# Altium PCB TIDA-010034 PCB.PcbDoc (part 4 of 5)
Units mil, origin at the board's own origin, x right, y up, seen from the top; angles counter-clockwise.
Board outline 4497.63 x 4881.81 mil, 4 copper layers (Top Layer, Signal Layer 1, Signal Layer 2, Bottom Layer), stack 62.18 mil thick; 483 components, 240 nets, 1255 pads, 589 vias.
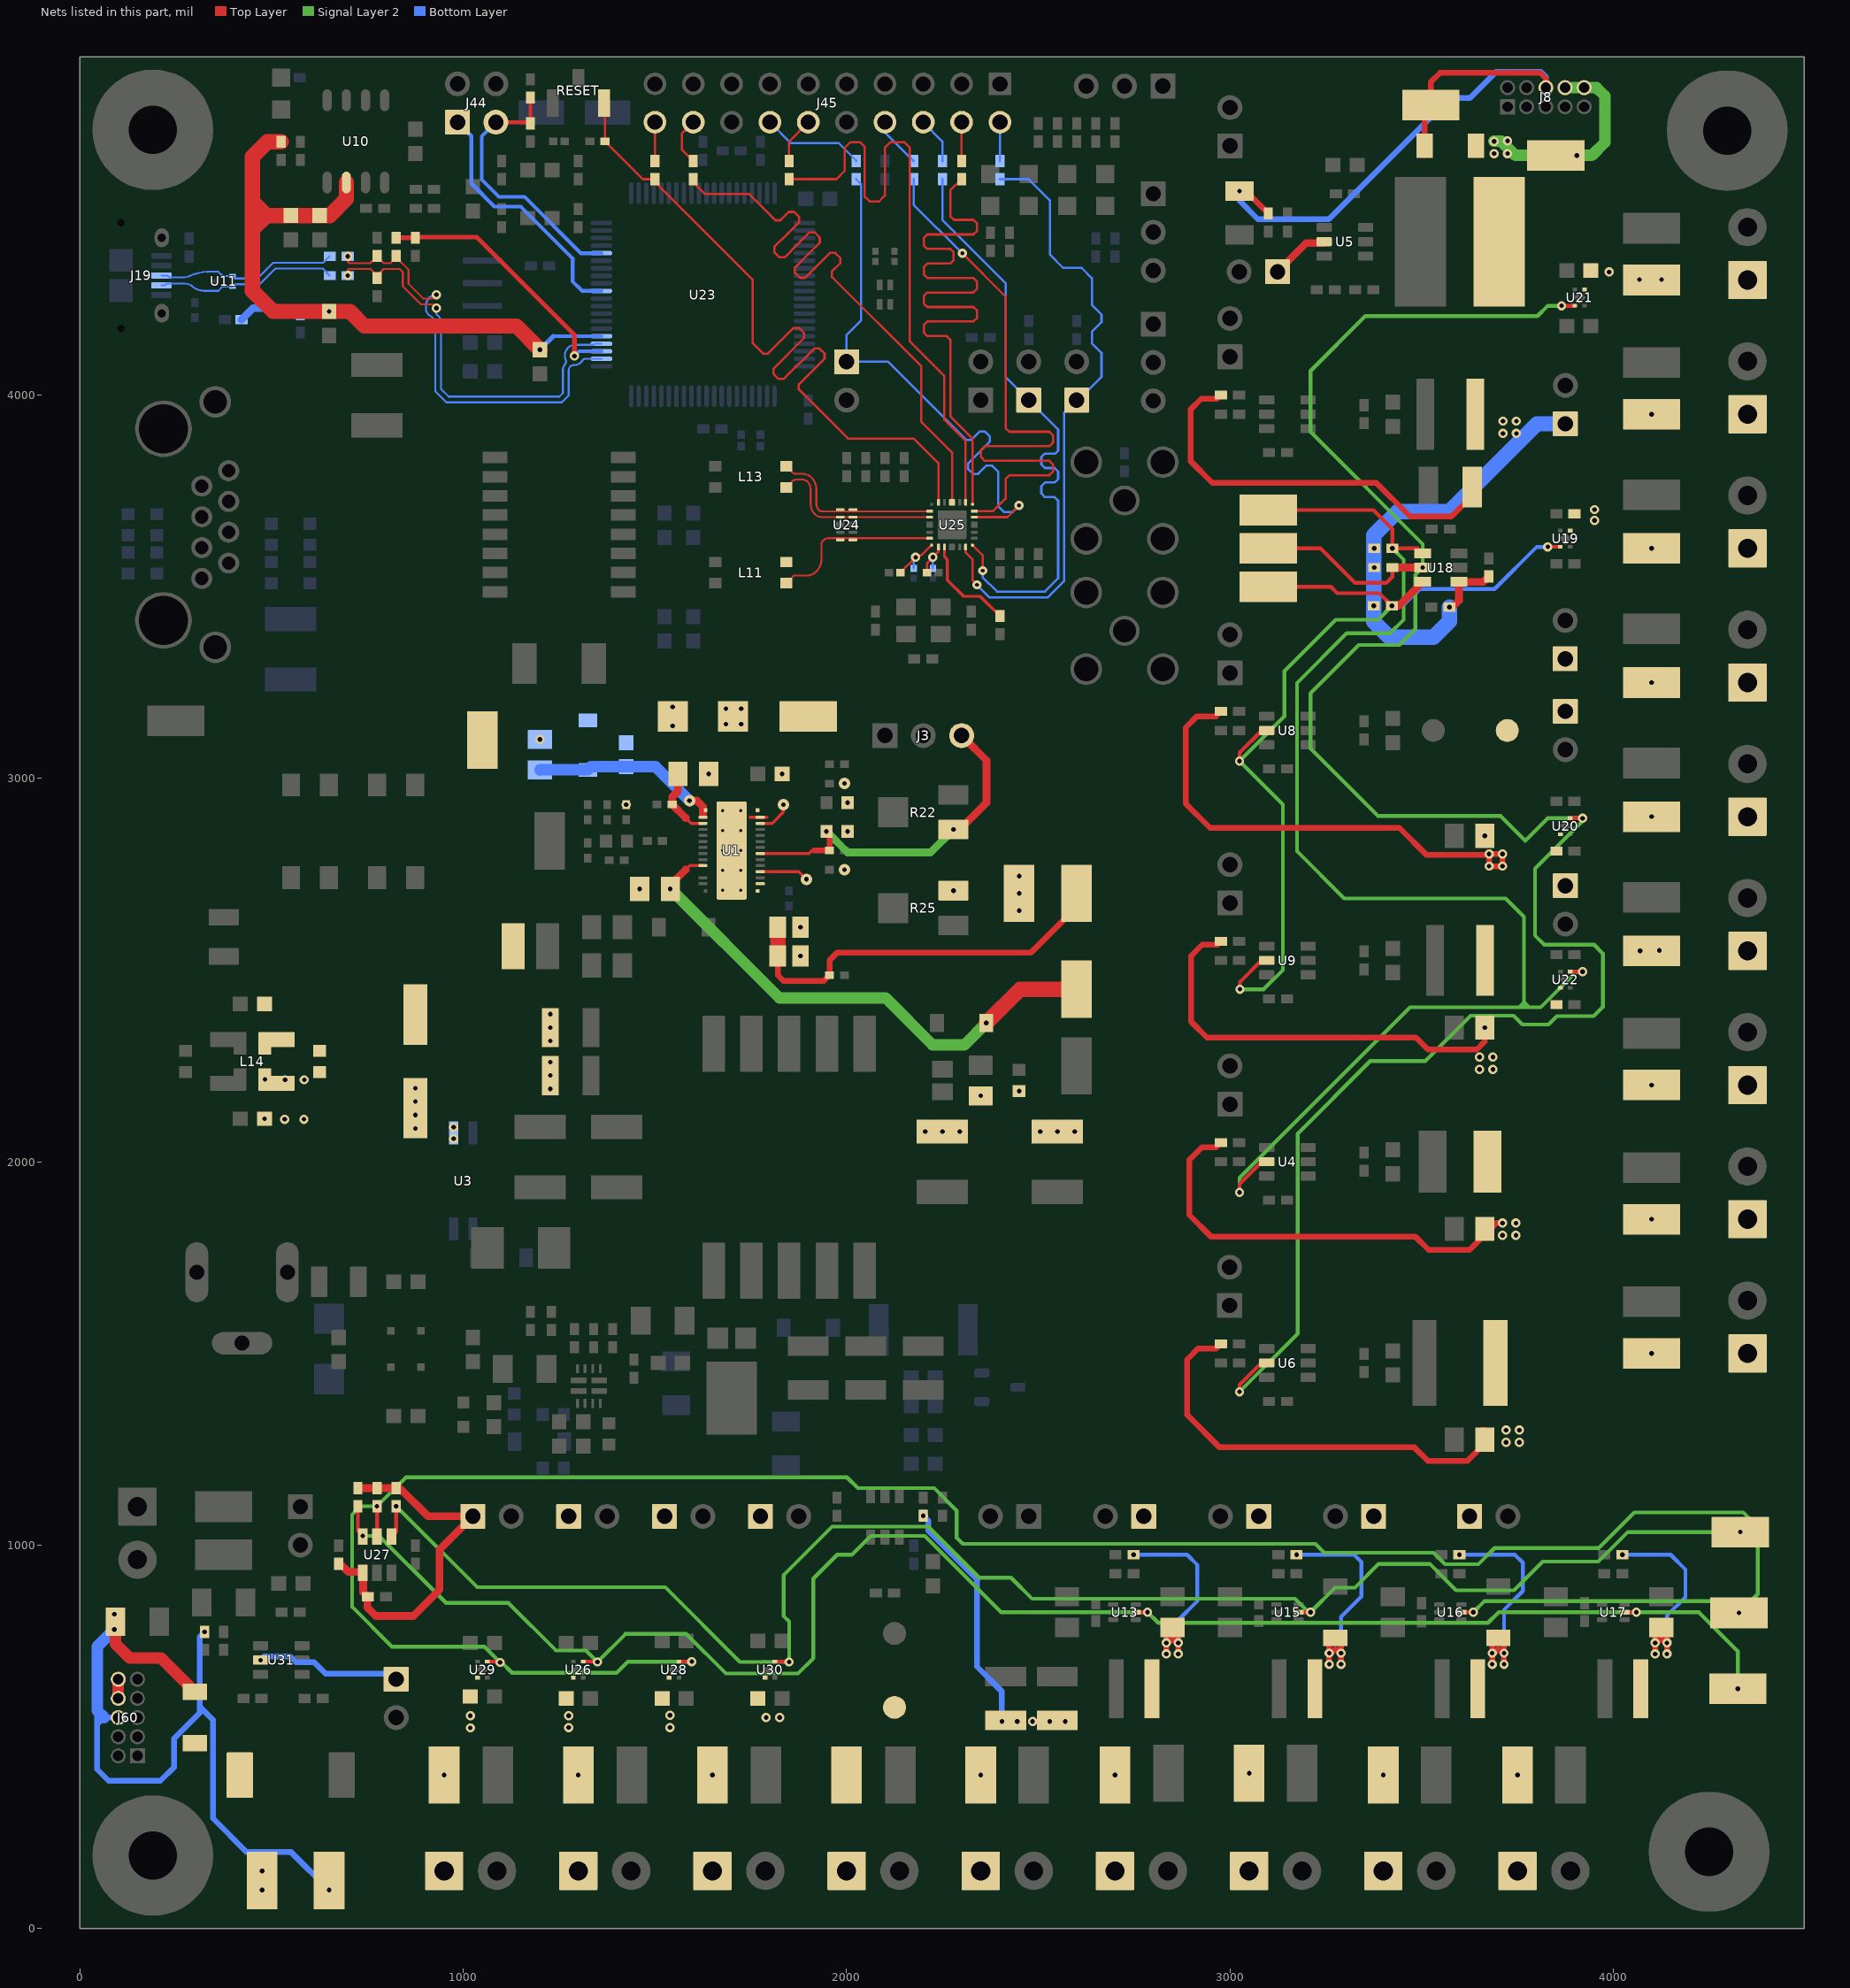
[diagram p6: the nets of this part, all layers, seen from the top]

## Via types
v1: diameter 24, hole 12, Top Layer to Bottom Layer, 451 vias
v2: diameter 30, hole 12, Top Layer to Bottom Layer, 86 vias
v3: diameter 24, hole 10, Top Layer to Bottom Layer, 22 vias
v4: diameter 19.68, hole 7.87, Top Layer to Bottom Layer, 10 vias
v5: diameter 20, hole 10, Top Layer to Bottom Layer, 8 vias
v6: diameter 19.69, hole 7.87, Top Layer to Bottom Layer, 5 vias
v7: diameter 18, hole 7.5, Top Layer to Bottom Layer, 3 vias
v8: diameter 20, hole 8, Top Layer to Bottom Layer, 2 vias
v9: diameter 34, hole 16, Top Layer to Bottom Layer, 2 vias

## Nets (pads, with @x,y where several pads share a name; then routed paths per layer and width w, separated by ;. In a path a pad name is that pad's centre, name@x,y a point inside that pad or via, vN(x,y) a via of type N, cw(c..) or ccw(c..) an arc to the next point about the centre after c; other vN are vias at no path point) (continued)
PGND: C4.2 C5.2 C6.2 C11.2 C13.2 C16.2 C24.2 C25.2 C27.1 C28.1 PGND.1 R5.1 R10.1 R11.1 R21.1 R25.1 R26.2 R28.1 U1.3 U1.11 U3.3 | length 220.7
  Top Layer w7.8: U1.3@1774.8,2756.69 1875.12,2756.69 v2(1895,2736.81) ; U1.11@1774.8,2882.68 1805.87,2882.68 1835,2911.81 v2(1835,2931.81)
  other v1: 975,2060 2205,2078.74 2250,2078.74 2295,2078.74 2505,2078.74 2550,2078.74 2595,2078.74 975,2090 2450,2655 2450,2700 2450,2745 1425,2931.5 1200,3101.81
  other v2: 875,2086.81 875,2121.81 875,2156.81 2350,2171.81 2450,2184.25 1226.85,2190 875,2191.81 1226.85,2225 1226.85,2260 1226.85,2315 1226.85,2350 1226.85,2385 1879.53,2536.81 1879.53,2611.81 2278.74,2707.09 1460,2711.81 1994.69,2761.81 2002.56,2861.81 2002.56,2936.81 1994.69,2986.81
PWDN: R87.2 U25.3 | length 1666.5
  Top Layer w6: R87.2@1600,4563.19 1600,4555 1630,4525 1745,4525 1807.5,4462.5 1814.2,4455.8 1827.59,4455.8 1849.57,4477.79 1862.96,4477.79 1876.35,4464.4 1876.35,4451.01 1847.67,4422.33 1811.49,4386.14 1811.49,4372.75 1824.88,4359.36 1838.27,4359.36 1874.45,4395.55 1903.14,4424.23 1916.53,4424.23 1929.92,4410.84 1929.92,4397.45 1901.23,4368.77 1865.05,4332.58 1865.05,4319.19 1878.44,4305.8 1891.83,4305.8 1928.01,4341.99 1956.7,4370.67 1970.09,4370.67 1983.48,4357.28 1983.48,4343.89 1961.49,4321.9 1961.49,4308.51 1965,4305 2195,4075 2195,3930 2275,3850 U25.3@2275,3719.88
PWDN_S: J45.18 R87.1 | length 126.2
  Top Layer w6: R87.1@1600,4610.43 1570,4640.43 1570,4681.81 J45.18@1600,4711.81
PWM1: J6.1 U5.5 | length 151.9
  Top Layer w20: J6.1@3124.02,4321.81 3199.02,4396.81 U5.5@3244.88,4396.81
PWM2: J58.1 U31.5 | length 383.1
  Bottom Layer w15: v1(470.87,700) 480.87,710 547.61,710 562.61,695 610,695 640,665 810,665 J58.1@825,650
RBIAS: R92.1 U25.14 | length 265.6
  Top Layer w7.87: U25.14@2255.32,3603.74 2255.32,3577.87 2263.19,3570 2263.19,3516.81 2305,3475 2348.62,3475 R92.1@2400,3423.62
RD_N: L13.4 U24.5 U24.6 U25.7 | length 456.3
  Top Layer w5: L13.4@1842.52,3814.37 1858.75,3798.14 ccw(c1868,3807.4) 1868,3794.31 1885.18,3794.31 cw(c1885.18,3761.18) 1908.61,3784.61 cw(c1878.69,3754.69) 1921,3754.69 1921,3716.82 ccw(c1945.34,3716.82) 1928.13,3699.6 ccw(c1934.73,3706.2) 1934.73,3696.87 2216.56,3696.87 U25.7@2216.93,3697.24
RD_P: L13.3 U24.4 U24.7 U25.8 | length 456.3
  Top Layer w5: L13.3@1842.52,3759.25 1858.75,3775.48 cw(c1868,3766.22) 1868,3779.31 1885.18,3779.31 cw(c1885.18,3761.18) 1898,3774 cw(c1878.69,3754.69) 1906,3754.69 1906,3716.82 ccw(c1945.34,3716.82) 1917.52,3689 ccw(c1934.73,3706.2) 1934.73,3681.87 2216.56,3681.87 U25.8@2216.93,3681.5
RESET: C123.2 R88.2 RESET.2 U25.5 | length 1969.3
  Top Layer w6: RESET.2@1366.93,4761.81 1369.69,4759.05 C123.2@1369.69,4661.81 1468.31,4563.19 R88.2@1500,4563.19 1500,4555 1755,4300 1755,4135 1775,4115 1781.7,4108.3 1795.09,4108.3 1862.07,4175.29 1875.46,4175.29 1888.85,4161.9 1888.85,4148.51 1815.17,4074.83 1808.99,4068.65 1808.99,4055.26 1822.38,4041.86 1835.77,4041.86 1841.95,4048.05 1915.64,4121.73 1929.03,4121.73 1942.42,4108.34 1942.42,4094.95 1875.43,4027.96 1875.43,4014.57 1880,4010 2003.19,3886.81 2175,3886.81 2239.57,3822.24 U25.5@2239.57,3719.88
RESET_S: J45.20 R88.1 | length 101.4
  Top Layer w6: R88.1@1500,4610.43 J45.20@1500,4711.81
RSNS: R10.2 R11.2 R13.2 RSNS.1 U1.1 U1.A1 | length 1048.6
  Top Layer w15: R10.2@1820.47,2536.81 1820.47,2486.34 1835,2471.81 1940.31,2471.81 R13.2@1955.32,2486.81 1955.32,2525.32 1975,2545 2480,2545 2600,2665 RSNS.1@2600,2700
  Top Layer w40: R10.2@1820.47,2536.81 R11.2@1820.47,2611.81
RST/SBWTDIO: C104.2 J44.3 R74.2 U23.76 | length 700.9
  Top Layer w10: J44.3@1085,4711.81 1171.81,4711.81 R74.2@1175,4715 ; R74.2@1175,4723.62 C104.2@1175,4776.38
  Bottom Layer w10: J44.3@1085,4711.81 1048,4674.81 1048,4562 1093,4517 1159.81,4517 1306.73,4370.08 U23.76@1360.24,4370.08
RX_D0: J52.1 R82.2 U25.18 | length 1619.7
  Top Layer w6: U25.18@2328.15,3608.66 2355,3581.81 v3(2355,3541.81)
  Bottom Layer w6: R82.2@2250,4563.19 2250,4456.81 2415,4291.81 2415,4046.81 J52.1@2475,3986.81 2551.81,3910 2551.81,3855 2544.37,3847.56 2517.47,3847.56 2508,3838.09 2508,3819.15 2517.47,3809.68 2542.34,3809.68 2551.81,3800.22 2551.81,3781.28 2542.34,3771.81 2517.47,3771.81 2508,3762.34 2508,3743.41 2517.47,3733.94 2542.34,3733.94 2551.81,3724.47 2551.81,3715 2551.81,3521.81 2517.56,3487.56 2392.44,3487.56 2355,3525 v3(2355,3541.81)
RX_D0_S: J45.6 R82.1 | length 122.1
  Bottom Layer w6: J45.6@2200,4711.81 2250,4661.81 R82.1@2250,4610.43
RX_D1: J51.1 R80.2 U25.17 | length 1664.1
  Top Layer w6: U25.17@2310.43,3603.74 2310.43,3589.57 2328.81,3571.19 2328.81,3516.19 v3(2340,3505)
  Bottom Layer w6: v3(2340,3505) 2373.19,3471.81 2524.08,3471.81 2567.56,3515.29 2567.56,3954.37 J51.1@2600,3986.81 2605,3986.81 2665,4046.81 2665,4110 2640,4135 2640,4165 2665,4190 2665,4210 2640,4235 2640,4305 2613.19,4331.81 2565,4331.81 2530,4366.81 2530,4508.19 2475,4563.19 R80.2@2400,4563.19
RX_D1_S: J45.2 R80.1 | length 101.4
  Bottom Layer w6: R80.1@2400,4610.43 J45.2@2400,4711.81
RX_ER: J49.1 R86.2 U25.22 | length 1465.3
  Top Layer w6: U25.22@2333.07,3681.5 2419.69,3681.5 v3(2450,3711.81)
  Bottom Layer w6: R86.2@2025,4563.19 2037.5,4550.69 2037.5,4194.31 2000,4156.81 J49.1@2000,4086.81 2108.19,4086.81 2285.22,3909.78 2298.61,3896.39 2305,3890 2311.7,3883.3 2325.09,3883.3 2347.05,3905.27 2360.44,3905.27 2373.83,3891.88 2373.83,3878.49 2345.17,3849.83 2316.51,3821.17 2316.51,3807.78 2329.9,3794.39 2343.29,3794.39 2365.26,3816.35 2378.65,3816.35 2387.5,3807.5 2395,3800 2395,3710 2410,3695 2433.19,3695 v3(2450,3711.81)
RX_ER_S: J45.14 R86.1 | length 267.8
  Bottom Layer w6: J45.14@1800,4711.81 1855,4656.81 1980,4656.81 2025,4611.81 R86.1@2025,4610.43
SEQ1_FLAG1: R66.1 SEQ1_FLAG1.1 U8.5 U9.5 U18.6 U19.3 | length 2540.4
  Top Layer w10: v1(3025,3045) 3025,3067 3083,3125 U8.5@3095.87,3125 ; v1(3026,2450) 3026,2469 3082,2525 U9.5@3095.87,2525 ; SEQ1_FLAG1.1@3100,3500 3263,3500 3280,3483 3389.64,3483 v1(3422.64,3450) ; v1(3829,3604) 3832.71,3604 3832.86,3604.14 U19.3@3861.76,3604.14
  Top Layer w20: v1(3422.64,3450) 3440.16,3450 U18.6@3502.76,3512.6
  Signal Layer 2 w10: v1(3026,2450) 3088,2450 3138,2500 3138,2932 v1(3025,3045) 3142,3162 3142,3280 3276,3414 3386.64,3414 v1(3422.64,3450)
  Bottom Layer w10: v1(3422.64,3450) 3451,3450 3495,3494 3690.27,3494 3800.27,3604 v1(3829,3604)
SEQ1_FLAG2: R67.1 SEQ1_FLAG2.1 U6.5 U18.5 U20.3 U21.3 | length 5880
  Top Layer w10: v1(3025,1400) 3025,1418 3082,1475 U6.5@3095.87,1475 ; SEQ1_FLAG2.1@3100,3600 3236,3600 3326,3510 3408,3510 3423.62,3525.62 R67.1@3423.62,3550 ; v1(3865.06,4232.96) U21.3@3899.5,4232.96 ; U20.3@3887.8,2896.06 3919.94,2896.06 v1(3920,2896)
  Top Layer w20: R67.1@3423.62,3550 v1(3502.76,3550)
  Signal Layer 2 w10: v1(3025,1400) 3177,1552 3177,2073.56 3366,2262.56 3509.56,2262.56 3628,2381 3740,2381 3763,2358 3831,2358 3852.87,2379.87 3948.87,2379.87 3972.63,2403.63 3972.63,2543.37 3950,2566 3820,2566 3795.87,2590.13 3795.87,2764.87 3920,2889 v1(3920,2896) 3828.8,2896 3770.4,2837.6 3706,2902 3386,2902 3210,3078 3210,3222 3336,3348 3442,3348 3484,3390 3484,3531.24 v1(3502.76,3550) 3502.76,3611.24 3210,3904 3210,4063 3353,4206 3802,4206 3828.96,4232.96 v1(3865.06,4232.96)
SEQ1_FLAG3: R68.1 SEQ1_FLAG3.1 U4.5 U18.4 U22.3 | length 3703.1
  Top Layer w10: v1(3025,1920) 3025,1942 3083,2000 U4.5@3095.87,2000 ; SEQ1_FLAG3.1@3100,3700 3374,3700 3423.62,3650.38 v1(3423.62,3600) 3490.16,3600 U18.4@3502.76,3587.4 ; U22.3@3887.8,2496.06 v1@3919.72,2496.06
  Signal Layer 2 w10: v1(3025,1920) 3025,1958 3470,2403 3755,2403 ; v1(3423.62,3600) 3453,3570.62 3453,3414 3418,3379 3305,3379 3175,3249 3175,2810 3298,2687 3719,2687 3767,2639 3767,2416.46 ; 3780.46,2403 3767,2416.46 ; v1(3920,2495.79) 3903.36,2495.79 3810.58,2403 3764,2403 ; 3755,2403 3764,2403 ; 3755,2403 3767,2415 ; 3764,2403 3767,2406 3767,2415 ; 3767,2415 3767,2416.46
SEQ2_FLAG1: R113.1 SEQ2_FLAG1.1 U13.5 U17.5 U26.3 U27.6 | length 4495.1
  Top Layer w10: R113.1@725,1101.38 725,1036.65 v1(737.6,1024.06) ; U26.3@1312.8,696.06 1348.94,696.06 v1(1350,695) ; U13.5@2754.13,825 v1(2785,825) ; U17.5@4029.13,825 v1(4060,825)
  Signal Layer 2 w10: v1(737.6,1024.06) 779.97,1024.06 955.02,849 1117.73,849 1241.73,725 1320,725 v1(1350,695) 1423,768 1582.02,768 1685.02,665 1873.45,665 1913,704.55 1913,912.69 1975.31,975 2014.01,975 2063.06,1024.06 2203.94,1024.06 2403,825 v1(2785,825) 2813,797 3673,797 3701,825 v1(4060,825) 4223,825 4325,723 v1(4325,625)
SEQ2_FLAG2: R114.1 SEQ2_FLAG2.1 U16.5 U27.5 U28.3 U29.3 | length 6263.8
  Top Layer w10: U27.5@775,1022.24 v1(775,1101.38) ; U29.3@1062.8,696.06 1093.94,696.06 v1(1096,694) ; U28.3@1562.8,696.06 v1@1595.94,696.06 ; U16.5@3604.14,825 v1(3635,825)
  Signal Layer 2 w10: v1(1596,696) 1429.46,696 1400.07,666.61 1127.39,666.61 1100,694 v1(1096,694) 1055,735 814,735 710,839 710,1079 732.38,1101.38 v1(775,1101.38) 850.62,1177 2001,1177 2029.5,1148.5 2228.5,1148.5 2287,1090 2287,1019 2303,1003 3223,1003 3246,980 3531,980 3561,950 3648,950 3690,992 3962,992 4055,1085 4339,1085 4377,1047 4377,872 v1(4328,823) 4297,854 3664.01,854 v1(3635,825)
SEQ2_FLAG3: R115.1 SEQ2_FLAG3.1 U15.5 U27.4 U30.3 | length 4362.7
  Top Layer w10: U27.4@812.4,1022.24 825,1034.84 v1(825,1101.38) ; U30.3@1812.8,696.06 1848.94,696.06 v1(1850,695) ; U15.5@3179.13,825 v1(3210,825)
  Signal Layer 2 w10: v1(825,1101.38) 1036.38,890 1526.73,890 1721.73,695 v1(1850,695) 1850,800.63 1835.5,815.13 1835.5,921.5 1962,1048 2213,1048 2346,915 2429,915 2484,860 3170,860 3205,825 v1(3210,825) 3274,889 3326,889 3388,951 3521,951 3590,882 3741,882 3816,957 3961,957 4038,1034 v1(4331,1034)
TARGET_D_N: C114.1 R78.1 U23.64 | length 1089.6
  Top Layer w5: v1(698.62,4311.81) 698.62,4325.62 702,4329 758,4329 C114.1@775,4312 ; C114.1@775,4305.43 C114.1@775,4312 ; v1(930,4226.81) 919.81,4237 889.07,4237 842,4284.07 842,4320.79 833.79,4329 792,4329 C114.1@775,4312
  Bottom Layer w5: v1(930,4226.81) ccw(c943.24,4219.17) 934,4207 cw(c919.21,4189.66) 942,4190 942,4016 961.91,3996.09 1250.83,3996.09 1260,4005.26 1260,4018 1260,4067 cw(c1282.6,4065.6) 1264.46,4079.15 ccw(c1255.15,4088.06) 1267.71,4090.93 cw(c1294.83,4103.77) 1264.85,4102.54 cw(c1292.15,4103.7) 1291,4131 1340,4131 1342.86,4133.86 U23.64@1360.24,4133.86
TARGET_D_P: C113.1 R75.2 R79.1 U23.62 | length 1151.4
  Top Layer w5: v1(698.62,4361.81) 698.62,4348.38 703,4344 757.16,4344 775,4361.84 C113.1@775,4363.19 ; C113.1@775,4361.82 792.82,4344 810,4344 R75.2@825,4359 ; R75.2@825,4363.19 R75.2@825,4359 ; v1(930,4261.81) 920.19,4252 895.28,4252 857,4290.28 857,4327 R75.2@825,4359
  Bottom Layer w5: v1(930,4261.81) ccw(c930,4234.81) 903,4234.81 903,4220 ccw(c929.64,4229.18) 917,4204 919.93,4201.07 cw(c902.86,4184) 927,4184 927,4009.79 955.7,3981.09 1257.05,3981.09 1275,3999.04 1275,4065 cw(c1288,4065) 1288,4078 ccw(c1288.93,4103.64) 1309.66,4088.52 cw(c1317.88,4085.87) 1318.49,4094.49 U23.62@1360.24,4094.49
TARGET_PUR: R75.1 R76.1 U23.63 | length 701
  Top Layer w12: R75.1@825,4410.43 R76.1@875,4410.43 ; R76.1@875,4411.81 1035,4411.81 1290,4156.81 v1(1290,4101.81)
  Bottom Layer w10: v1(1290,4101.81) 1302.36,4114.18 U23.63@1360.24,4114.18
TD_N: U24.2 U24.9 U25.10 | length 455
  Top Layer w5: 1842.52,3564.37 1860.87,3546.02 ; 1860.88,3546.01 ccw(c1865,3550.16) 1865,3544.31 1896.36,3544.31 ccw(c1896.36,3563.6) 1910,3549.96 ccw(c1887.59,3572.37) 1919.28,3572.37 1919.28,3609.61 cw(c1950.39,3609.61) 1928.39,3631.61 cw(c1952.89,3607.11) 1952.89,3641.75 2216.56,3641.75 U25.10@2216.93,3642.13
TD_N: L11.4
TD_P: L11.3 U24.1 U24.10 U25.11 | length 455
  Top Layer w5: L11.3@1842.52,3509.25 1860.87,3527.6 ; 1860.88,3527.61 cw(c1865,3523.47) 1865,3529.31 1896.36,3529.31 ccw(c1896.36,3563.6) 1920.61,3539.35 ccw(c1887.59,3572.37) 1934.28,3572.37 1934.28,3609.61 cw(c1950.39,3609.61) 1939,3621 cw(c1952.89,3607.11) 1952.89,3626.75 2216.56,3626.75 U25.11@2216.93,3626.38
TEST/SBWTCK: J44.1 U23.71 | length 665.2
  Bottom Layer w10: J44.1@985,4711.81 1021,4675.81 1021,4552 1081.19,4491.81 1150,4491.81 1285,4356.81 1285,4296.81 1310.16,4271.66 U23.71@1360.24,4271.66
TX_D0: R83.2 U25.23 | length 1605.4
  Top Layer w6: v3(2301.81,4370) 2415,4256.81 2415,3923.22 2415,3913.75 2424.47,3904.28 2528.87,3904.28 2538.34,3894.81 2538.34,3875.87 2528.87,3866.41 2415,3866.41 2360.3,3866.41 2350.83,3856.94 2350.83,3838 2360.3,3828.53 2415,3828.53 2528.87,3828.53 2538.34,3819.06 2538.34,3800.13 2528.87,3790.66 2424.47,3790.66 2415,3781.19 2415,3780 2415,3730 2382.24,3697.24 U25.23@2333.07,3697.24
  Bottom Layer w6: R83.2@2175,4563.19 2175,4496.81 v3(2301.81,4370)
TX_D0_S: J45.8 R83.1 | length 132.4
  Bottom Layer w6: J45.8@2100,4711.81 2100,4685.43 R83.1@2175,4610.43
TX_D1: R81.2 U25.24 | length 1775
  Top Layer w6: R81.2@2300,4563.19 2270.75,4533.94 2270.75,4495 2270.75,4466.4 2280.22,4456.93 2330.77,4456.93 2340.24,4447.46 2340.24,4428.52 2330.77,4419.05 2270.75,4419.05 2210.73,4419.05 2201.26,4409.59 2201.26,4390.65 2210.73,4381.18 2270.75,4381.18 2278.94,4372.99 2278.94,4351.5 2270.75,4343.31 2210.73,4343.31 2201.26,4333.84 2201.26,4314.9 2210.73,4305.43 2270.75,4305.43 2330.77,4305.43 2340.24,4295.96 2340.24,4277.03 2330.77,4267.56 2270.75,4267.56 2210.73,4267.56 2201.26,4258.09 2201.26,4239.15 2210.73,4229.68 2270.75,4229.68 2330.77,4229.68 2340.24,4220.22 2340.24,4201.28 2330.77,4191.81 2270.75,4191.81 2210.73,4191.81 2201.26,4182.34 2201.26,4163.41 2210.73,4153.94 2261.28,4153.94 2270.75,4144.47 2270.75,4135 2270.75,3944.25 2328.15,3886.85 U25.24@2328.15,3714.96
TX_D1_S: J45.4 R81.1 | length 101.4
  Top Layer w6: R81.1@2300,4610.43 J45.4@2300,4711.81
TX_EN: R85.2 U25.1 | length 1659.7
  Top Layer w6: R85.2@1850,4563.19 1973.19,4563.19 1995,4585 1995,4645 2010,4660 2035,4660 2046.65,4648.35 2046.65,4518.35 2060,4505 2085,4505 2100,4520 2100,4645 2115,4660 2150,4660 2165,4645 2165,4140 2255,4050 2255,3935 2310.43,3879.57 2310.43,3871.99 2310.5,3871.93 2310.5,3765.06 2310.43,3765 U25.1@2310.43,3719.88
TX_EN_S: J45.12 R85.1 | length 122.1
  Top Layer w6: R85.1@1850,4610.43 1850,4661.81 J45.12@1900,4711.81
USB_N: J19.2 R78.2 U11.2 | length 484.1
  Bottom Layer w5: J19.2@212.4,4286.22 221.22,4286.22 226,4291 269.77,4291 cw(c271.29,4253.72) 290,4286 ccw(c324.7,4321.8) 322.31,4272 337.02,4271.96 ; R78.2@651.38,4311.81 633.19,4330 510,4330 469,4289 403.61,4289 U11.2@397.64,4283.03 372.03,4283.03 360.94,4271.94 344.01,4271.94 ; 337.02,4271.96 344.01,4271.94 ; 337.02,4271.94 344.01,4271.94
USB_P: J19.3 R79.2 U11.1 | length 474.4
  Bottom Layer w5: J19.3@212.4,4311.81 228.19,4311.81 233,4307 268,4307 ccw(c269.52,4344.28) 288.23,4312 cw(c338.97,4185.26) 344.01,4321.69 360.94,4321.69 372.03,4310.59 U11.1@397.64,4310.59 404.23,4304 463,4304 504,4345 634.57,4345 R79.2@651.38,4361.81
USB_VBUS: C64.1 C65.1 C70.1 C71.1 C107.2 D12.1 D13.1 R49.2 U10.2 U23.65 | length 2052.7
  Top Layer w40: R49.2@525,4660.43 488.62,4660.43 450,4621.81 450,4504.8 ; U10.2@695,4554.53 695,4511.81 651.5,4468.31 C64.1@625,4468.31 C65.1@550,4468.31 486.5,4468.31 ; v2(1200,4118.31) 1138.31,4180 741.81,4180 703.5,4218.31 v2(650,4218.31) 503.5,4218.31 450,4271.81 450,4431.81 ; 450,4431.81 450,4504.8 ; 450,4431.81 486.5,4468.31 ; 450,4504.8 486.5,4468.31
  Bottom Layer w10: 1235.24,4153.55 U23.65@1360.24,4153.55
  Bottom Layer w12: v2(1200,4118.31) 1235.24,4153.55
  Bottom Layer w20: D12.1@421.65,4196.81 451.65,4226.81 558.62,4226.81 C70.1@575,4210.43 582.87,4218.31 v2(650,4218.31)
VB: C25.1 J3.3 R22.3 R23.1 U1.6 | length 919
  Top Layer w7.8: U1.6@1774.8,2803.94 1902.13,2803.94 1910,2811.81 1915,2811.81
  Top Layer w15: 1915,2811.81 R23.1@1955.32,2811.81 1955.32,2853.94 v2(1947.44,2861.81)
  Top Layer w20: v2(2278.74,2866.54) 2294.72,2866.54 2365,2936.81 2365,3046.81 J3.3@2310,3101.81
  Signal Layer 2 w20: v2(1947.44,2861.81) 2002.44,2806.81 2219.02,2806.81 v2(2278.74,2866.54)
VCC: C16.1 D4.1 U1.21 VCC.1 | length 1404.7
  Top Layer w7.8: 1580,2761.81 1590.63,2772.44 U1.21@1625.2,2772.44
  Top Layer w20: v2(1540,2711.81) 1540,2721.81 1580,2761.81
  Top Layer w40: v2(2364.47,2361.81) 2452.66,2450 VCC.1@2600,2450
  Signal Layer 2 w30: v2(1540,2711.81) 1824.81,2427 2102,2427 2224,2305 2307.66,2305 v2(2364.47,2361.81)
VDD: C13.1 D6.1 R8.1 U1.13 U1.A3 | length 499.5
  Top Layer w7.8: U1.13@1625.2,2898.43 1625.2,2906.61
  Top Layer w20: v2(1590,2941.81) 1609.36,2941.81 1625.2,2925.97 1625.2,2906.61
  Bottom Layer w30: C13.1@1200,3021.81 1200.53,3022.34 D6.1@1325,3022.34 1332.97,3030.32 R8.1@1425,3030.32 1501.5,3030.32 v2(1590,2941.81)
VDD1_1.1V: 1.1V.1@4100,1850 C31.1 J9.1 L5.2 R30.2 | length 1128.7
  Top Layer w15: R30.2@2976.38,2050 2964.38,2038 2927,2038 2894,2005 2894,1861 2950,1805 3483,1805 3518,1770 3625,1770 3695,1840 v1(3711,1840)
  other v1: 3711,1808 3746,1808 3746,1840 4100,1850
VDD1_1.5V_Img: 1.5VA.1@4100,2550 C102.1 J43.1 U22.1
  other v1: 4070,2550 4120,2551
VDD1_1.8V_codec: 1.8VD.1@4100,2200 C51.1 J17.1 L10.2 R41.2 | length 1105.8
  Top Layer w15: R41.2@2976.38,2575 2967.38,2566 2927.69,2566 2899,2537.31 2899,2365 2940,2324 3485.34,2324 3516.34,2293 3644,2293 3665,2314 v1(3665,2350)
  other v1: 4100,2200 3651,2241 3686,2241 3651,2273 3686,2273
VDD1_1.8V_Img: 1.8VA.1@4100,3600 C96.1 J34.1 U19.1
  other v1: 4100,3600 3950.87,3673.06 3950.94,3701.24
VDD1_1.35V: 1.35V.1@4100,1500 C40.1 J12.1 L7.2 R35.2 | length 1152.2
  Top Layer w15: R35.2@2976.38,1525 2964.38,1513 2917,1513 2888,1484 2888,1340 2973,1255 3480.95,1255 3515.95,1220 3620,1220 3678.5,1278.5 3657,1300 C40.1@3665,1300
  other v1: 3720,1268 3755,1268 3720,1300 3755,1300 4100,1500
VDD1_2.8V_Img: 2.8VA.1@4100,2900 C98.1 J39.1 U20.1
  other v1: 4100,2900
VDD1_3.3V: 3.3V.1 C47.1 J15.1 J32.1 J35.1 J41.1 L9.2 R39.2 | length 1275.3
  Top Layer w15: R39.2@2976.38,3175 2963.38,3162 2914,3162 2885,3133 2885,2934 2948,2871 3441.93,2871 3512.93,2800 v1@3665,2800 ; v1@3676,2801 v1(3676,2771) v1(3711,2771) v1(3711,2803) v1(3676,2803)
  other v1: 3665,2850 4100,3250
VDD1_3.3VA: 3.3VA.1@4100,4300 C99.1 J40.1 U21.1
  other v1: 3988.94,4321.06
  other v2: 4068,4301 4126,4301
VDD1_5V: 5V.1@4100,3950 C43.1 C95.1 J13.1 J37.1 L8.2 R36.2 R66.2 R67.2 R68.2 R111.2 U18.1 | length 2312.6
  Top Layer w15: R36.2@2976.38,4000 2966.38,3990 2925,3990 2897,3962 2897,3828 2954,3771 3381.8,3771 3469.8,3683 3577.57,3683 C43.1@3632.09,3737.52
  Top Layer w20: C95.1@3583.61,3450.39 3597.24,3464.02 U18.1@3597.24,3512.6 3660.84,3512.6 R111.2@3675,3526.76
  Bottom Layer w40: v1(3572.64,3446.81) 3572.64,3409.64 3531,3368 3416,3368 3375.39,3408.61 v1(3375.39,3450) 3375.39,3634.39 3437,3696 3572,3696 3801,3925 J37.1@3875,3925
  other v1: 3376.38,3550 3376.38,3600 3712,3900 3747,3900 3712,3932 3747,3932 4100,3950
VDD2_1.1V: 1.1V.1@3050,405 C86.1 J27.1 L21.2 R60.2 | length 579
  Top Layer w15: v1(3259,689.07) 3259,713.07 3275,729.07 3290,714.07 v1(3290,689.07) ; v1(3259,718.07) C86.1@3259,742.07 ; v1(3290,718.07) C86.1@3290,743.07
  Bottom Layer w10: v1(3173.62,975) 3324,975 3343,956 3343,866 3290,813 v1(3290,718.07)
  other v1: 3050,405
VDD2_1.5V_Img: 1.5VA.1@2000,400 C135.1 J57.1 U30.1
  other v1: 1790,550 1825.25,550
VDD2_1.8V_Codec: 1.8VD.1@3750,400 C92.1 J31.1 L23.2 R64.2 | length 533.5
  Top Layer w15: v1(4109,716) 4109,740 4125,756 4140,741 v1(4140,716) ; v1(4109,745) C92.1@4109,769 ; v1(4140,745) C92.1@4140,770
  Bottom Layer w10: v1(4023.62,975) 4149.37,975 4188,936.37 4188,864 4140,816 v1(4140,745)
  other v1: 3750,400
VDD2_1.8V_Img: 1.8VA.1@1300,400 C129.1 J36.1 U26.1
  other v1: 1300,400 1275,524 1275,555
VDD2_1.35V: 1.35V.1@3400,400 C89.1 J29.1 L22.2 R62.2 | length 572.1
  Top Layer w15: v1(3684,689.07) 3684,713.07 3700,729.07 3715,714.07 v1(3715,689.07) ; v1(3684,718.07) C89.1@3684,742.07 ; v1(3715,718.07) C89.1@3715,743.07
  Bottom Layer w10: v1(3598.62,975) 3743,975 3764,954 3764,880.37 3715,831.37 v1(3715,718.07)
  other v1: 3400,400
VDD2_2.8V_Img: 2.8VA.1@1650,400 C131.1 J54.1 U28.1
  other v1: 1650,400 1539,524 1539,556
VDD2_3.3V: 3.3VD.1 C77.1 J24.1 L18.2 R56.2 | length 587
  Top Layer w15: v1(2834,716) 2834,740 2850,756 2865,741 v1(2865,716) ; v1(2834,745) 2834,769 C77.1@2850,785 2865,770 v1(2865,745)
  Bottom Layer w10: v1(2748.62,975) 2888,975 2915,948 2915,854 2865,804 v1(2865,745)
  other v1: 2700,400
VDD2_3.3VA: 3.3VA.1@950,400 C132.1 J55.1 U29.1
  other v1: 950,400 1018.5,523 1018.5,555
VDD2_5V: 5V.1@2350,400 C78.1 C81.1 C82.1 C128.1 J22.1 J25.1 J26.1 J28.1 J30.1 J33.1 J38.1 J42.1 J56.1 L19.2 R57.2 R113.2 R114.2 R115.2 R116.2 U27.1 | length 1578.6
  Top Layer w20: C128.1@676.38,953.19 700,929.57 738.98,929.57 738.98,877.4 R116.2@750,866.38 ; R113.2@725,1148.62 R114.2@775,1148.62 R115.2@825,1148.62 834.38,1148.62 908,1075 J38.1@1025,1075 938,988 938,883.38 869.62,815 772,815 750,837 R116.2@750,866.38 ; R116.2@750,868.62 R116.2@750,866.38 ; R116.2@751.38,865 R116.2@750,866.38
  Bottom Layer w15: v1(2200,1076.38) 2213,1063.38 2213,1037 2340,910 2340,683 2405,618 v1(2405,540)
  other v1: 2350,400 2445,540 2485,540 2530,540 2570,540
VLED1: C32.1 J8.8 J8.10 L6.2 VLED1.1 | length 552.4
  Signal Layer 2 w30: v1(3689,4662) 3707.6,4662 3744.6,4625 v2(3905,4625) 3944,4625 3978,4659 3978,4780 3956.19,4801.81 J8.10@3924.02,4801.81 J8.8@3874.02,4801.81
  other v1: 3689,4630 3724,4630 3724,4663
VLED1_FB: C32.2 J8.6 R33.2 R34.2 VLED1_FB.1 | length 1700.1
  Top Layer w15: v1(3025,4532.09) 3041.54,4532.09 R33.2@3100,4473.62 ; C32.2@3508.07,4625 C32.2@3508.07,4650 3508.07,4731.07 3524.02,4747.02 VLED1_FB.1@3524.02,4756.81 3524.02,4817.02 3548,4841 3809,4841 3824.02,4825.98 J8.6@3824.02,4801.81
  Top Layer w30: VLED1_FB.1@3508.07,4738.9 3507.09,4739.88 VLED1_FB.1@3524.02,4756.81
  Bottom Layer w15: v1(3025,4532.09) 3025,4507.09 3073.09,4459 3258,4459 3574,4775 3626,4775 3694,4843 3811,4843 3824.02,4829.98 J8.6@3824.02,4801.81
VLED2: C138.1 J60.8 J60.10 L20.2 VLED2.1 | length 100
  Top Layer w30: J60.8@100,600 J60.10@100,650
  Bottom Layer w30: J60.8@100,600 J60.10@100,650
  other v1: 475,100 475,150
VLED2_FB: C138.2 J60.6 R119.2 R120.2 VLED2_FB.1 | length 2148.8
  Top Layer w30: v1(90,820) 90,790.83 92.91,787.91 92.91,742.09 130,705 211.93,705 C138.2@300,616.93
  Bottom Layer w15: 45,568 45,532 ; J60.6@100,550 63,550 45,532 ; v1(325,773.62) 313,761.62 313,578 ; v1(650,100) 551,199 435,199 347,287 347,544 313,578 ; 45,532 45,415 75,385 210,385 245,420 245,495 313,563 313,578
  Bottom Layer w30: 63,550 45,568 45,735 v1(90,780) v1(90,820)
VPD: C4.1 C14.1 C55.1 D6.2 D10.1 L1.1 L12.2 L14.3 L14.@512.99,2318.9 R8.2 R12.1 U1.14 VPD.1 | length 187.2
  Top Layer w7.8: 1580,2896.81 1594.13,2882.68 U1.14@1625.2,2882.68
  Top Layer w20: C14.1@1560,3011.81 1560,2966.81 1544.69,2951.5 R12.1@1544.69,2931.81 1545,2931.81 1580,2896.81
  other v1: 1546.26,3136.81 1546.26,3186.81
VSS: C14.2 C55.2 D10.2 L14.2 L14.@512.99,2204.72 L15.2 R17.1 U1.12 U1.25 U1.A2 VSS.1 | length 43.2
  Top Layer w7.8: 1748.39,2898.43 U1.12@1774.8,2898.43 1791.61,2898.43
  other v1: 534.02,2110.83 584.25,2110.83 481.5,2111.81 535,2213.58 585.24,2213.58 482.48,2214.57
  other v2: 1640,3011.81 1831.5,3011.81 1685,3141.81 1725,3141.81 1685,3181.81 1725,3181.81
  other v4: 1676.38,2707.87 1723.62,2707.87 1676.38,2759.84 1723.62,2759.84 1676.38,2811.81 1723.62,2811.81 1676.38,2863.78 1723.62,2863.78 1676.38,2915.75 1723.62,2915.75
XI: R105.2 R108.2 U25.13 | length 108.2
  Top Layer w6: R105.2@2210.04,3536.81 R105.2@2210.04,3536.81 2210,3561.81 2239.57,3591.38 U25.13@2239.57,3603.74
  Bottom Layer w6: R108.2@2225,3547.99 v1(2225,3577)
XO: R100.2 R124.2 U25.12 | length 142.6
  Top Layer w6: R100.2@2139.96,3536.81 v1(2180,3576.85) 2184.96,3581.81 2195,3581.81 U25.12@2221.85,3608.66
  Bottom Layer w6: R124.2@2175,3547.99 2175,3571.85 v1(2180,3576.85)
pads on no net: H1.1 H2.1 H3.1 H4.1 J8.2 J8.3 J8.4 J8.5 J8.7 J8.9 J19.4 J45.16 J60.2 J60.3 J60.4 J60.5 J60.7 J60.9 T1.5 T1.6 T2.4 T2.5 T2.12 T2.13 U1. U1.17 U1.23 U13.6 U15.6 U16.6 U17.6 U23.1 U23.2 U23.3 U23.4 U23.5 U23.6 U23.7 U23.8 U23.9 U23.10 U23.12 U23.13 U23.15 U23.16 U23.17 U23.23 U23.24 U23.25 U23.26 U23.27 U23.28 U23.29 U23.30 U23.31 U23.32 U23.33 U23.34 U23.35 U23.36 U23.37 U23.38 U23.39 U23.40 U23.41 U23.42 U23.43 U23.44 U23.45 U23.48 U23.51 U23.52 U23.53 U23.54 U23.55 U23.56 U23.57 U23.58 U23.59 U23.60 U23.72 U23.73 U23.74 U23.75 U23.77 U23.78 U23.79 U23.80 U24.3@2016.44,3661.81 U24.8@1983.56,3661.81 U25.

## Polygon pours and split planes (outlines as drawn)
GND on Top Layer "Top Layer-No Net 36" (solid, remove dead copper, pour order 664): 24 vertices, not listed, extent 0,0 4497.63,4883
NetC103_1 on Top Layer "Top Layer-No Net 21" (solid, pour order 662): 3921.25,2654 3929.88,2644.99 3929.88,2588.88 3910,2569 3880,2569 3868,2557 3868,2491 3859,2482 3815.46,2482 3815.46,2644.46 3825,2654
VDD1_2.8V_Img on Top Layer "Top Layer-No Net 29" (solid, pour order 660): 20 vertices, not listed, extent 3800,2763 4420,2961
NetC100_1 on Top Layer "Top Layer-No Net 21" (solid, pour order 658): 3915.21,3115 3929.88,3099.69 3929.88,2989.88 3910,2970 3880,2970 3868,2958 3868,2892 3859,2883 3815.46,2883 3815.46,3099.69 3830.77,3115
NetC97_1 on Top Layer "Top Layer-No Net 26" (solid, pour order 656): 3881,3609 3889,3617 3893,3617 3932,3617 3932,3380 3922,3370 3816,3370 3806,3380 3806,3491 3816,3501 3871,3501 3881,3511
NetC101_1 on Top Layer "Top Layer-No Net 26" (solid, pour order 654): 3919,4238 3927,4246 3931,4246 3970,4246 3970,4000 3960,3990 3810,3990 3800,4000 3800,4100 3830,4130 3909,4130 3919,4140
VDD1_3.3VA on Top Layer "Top Layer-No Net 18" (solid, pour order 652): 4409.98,4360 4419.98,4350 4420,4230 4410.09,4220.09 4020,4220 3978,4262 3928,4262 3918,4272 3918,4352 3926,4360
NetC136_1 on Top Layer "Top Layer-No Net 17" (solid, pour order 650): 1920,1120 1920,916.87 1793.13,790 1793,691 1784,682 1740,682 1730,692 1730,882 1830,982 1830,1120
NetC133_1 on Top Layer "Top Layer-No Net 17" (solid, pour order 648): 1670,1120 1670,916.87 1543.13,790 1543,691 1534,682 1490,682 1480,692 1480,882 1580,982 1580,1120
NetC130_1 on Top Layer "Top Layer-No Net 17" (solid, pour order 646): 1420,1120 1420,916.87 1293.13,790 1293,691 1284,682 1240,682 1230,692 1230,882 1330,982 1330,1120
NetC134_1 on Top Layer "Top Layer-No Net 14" (solid, pour order 644): 1000,683 1035.06,682.87 1044,691.81 1044,826 1170,952 1170,1120 1090,1120 1090,1020.81 990,920.81 990,683 999,683
VDD2_1.8V_Codec on Top Layer "Top Layer-No Net 48" (solid, pour order 616): 20 vertices, not listed, extent 3680,30 4175,815
NetC93_1 on Top Layer "Top Layer-No Net 47" (solid, pour order 614): 3985,810 3985,780 3945,740 3770,740 3760,750 3760,970 3750,980 3690,980 3680,990 3680,1119 3690,1129 3790,1129 3800,1119 3800,820 3810,810
NetC90_1 on Top Layer "Top Layer-No Net 35" (solid, pour order 612): 19 vertices, not listed, extent 3230,740 3560,1119
VDD2_1.35V on Top Layer "Top Layer-No Net 34" (solid, pour order 610): 22 vertices, not listed, extent 3320,30 3745,820
NetL23_1 on Top Layer "Top Layer-No Net 43" (solid, pour order 608): 4045,810 4045,760 4044,760 4005,721 4005,545 3955,545 3955,717 4015,777 4015,810
NetL22_1 on Top Layer "Top Layer-No Net 43" (solid, pour order 606): 3620,810 3620,760 3619,760 3580,721 3580,545 3530,545 3530,717 3590,777 3590,810
NetL21_1 on Top Layer "Top Layer-No Net 43" (solid, pour order 604): 3195,810 3195,760 3194,760 3155,721 3155,545 3105,545 3105,717 3165,777 3165,810
VDD2_1.1V on Top Layer "Top Layer-No Net 46" (solid, pour order 602): 20 vertices, not listed, extent 2950,30 3320,820
NetC87_1 on Top Layer "Top Layer-No Net 45" (solid, pour order 600): 18 vertices, not listed, extent 2905,740 3135,1129
VDD2_3.3V on Top Layer "Top Layer-No Net 44" (solid, pour order 598): 19 vertices, not listed, extent 2620,30 2890,820
NetL18_1 on Top Layer "Top Layer-No Net 43" (solid, pour order 596): 2770,810 2770,760 2769,760 2730,721 2730,545 2680,545 2680,717 2740,777 2740,810
NetC79_1 on Top Layer "Top Layer-No Net 42" (solid, pour order 594): 25 vertices, not listed, extent 2440,740 2720,1128
NetC83_1 on Top Layer "Top Layer-No Net 41" (solid, pour order 554): 26 vertices, not listed, extent 2105,855 2420,1128
NetC76_1 on Top Layer "Top Layer-No Net 22" (solid, pour order 548): 2115,1041 2115,986 2120,981 2126,981 2130,977 2130,920 2125,915 2075,915 2070,920 2070,976 2075,981 2081,981 2085,985 2085,1041
GND on Top Layer "gn" (solid, remove dead copper, pour order 110): 2340.91,651.19 2364.09,628 2587.91,628 2597.91,638 2597.91,710.09 2588,720 2351,720 2340.91,709.91
NetC39_1 on Top Layer "Top Layer-No Net 25" (solid, pour order 542): 3475,4045 3533,4045 3533,3855 3475,3855
NetC39_1 on Top Layer "Top Layer-No Net 22" (solid, pour order 540): 3184,3965 3239,3965 3244,3970 3244,3976 3248,3980 3305,3980 3310,3975 3310,3925 3305,3920 3249,3920 3244,3925 3244,3931 3240,3935 3184,3935
NetC44_1 on Top Layer "Top Layer-No Net 23" (solid, pour order 538): 20 vertices, not listed, extent 2940,3955.41 3454.76,4240
NetC46_1 on Top Layer "Top Layer-No Net 22" (solid, pour order 532): 3184,3140 3239,3140 3244,3145 3244,3151 3248,3155 3305,3155 3310,3150 3310,3100 3305,3095 3249,3095 3244,3100 3244,3106 3240,3110 3184,3110
NetC48_1 on Top Layer "Top Layer-No Net 23" (solid, pour order 530): 20 vertices, not listed, extent 2940,3130.41 3454.76,3415
VDD1_1.8V_codec on Top Layer "Top Layer-No Net 39" (solid, pour order 476): 3640,2650 3700,2650 3710,2640 3710,2370 3750,2330 3870,2330 3940,2260 4410,2260 4420,2250 4420,2140 4410,2130 3920,2130 3692,2130 3630,2192 3630,2640
VDD1_1.5V_Img on Top Layer "Top Layer-No Net 38" (solid, pour order 474): 19 vertices, not listed, extent 3795,2345 4420,2615
GND on Top Layer "Top Layer-No Net 20" (solid, remove dead copper, pour order 472): 4040.92,2410.02 4409.98,2410.02 4420,2400 4420,2294 4410,2284 4032,2284 4019.91,2296.09 4019.91,2390.92
GND on Top Layer "Top Layer-No Net 20" (solid, remove dead copper, pour order 470): 3955.38,2745.71 4410.29,2745.71 4420,2736 4420,2644 4410,2634 3954,2634 3945,2643 3945,2736.27
VLED1 on Top Layer "Top Layer-No Net 31" (solid, pour order 446): 3610,4660 3640,4690 3930,4690 3940,4680 3940,4570 3900,4530 3820,4530 3790,4500 3790,4230 3770,4210 3630,4210 3610,4230
VDD2_2.8V_Img on Top Layer "Top Layer-No Net 24" (solid, pour order 406): 18 vertices, not listed, extent 1496.73,30 1704,666.76
PGND on Top Layer "Top Layer-PGND" (solid, remove dead copper, pour order 372): 30,3065 30,2140 165,2005 2620,2005 2775,2160 2775,3050 2640,3185 150,3185
EARTH_GND on Top Layer "BSP" (solid, remove dead copper, pour order 358): 30,3980 100,4050 465,4050 553.19,3961.81 878.19,3961.81 930,3910 1585,3910 1780,3715 1780,3280 1730,3230 105,3230 30,3305
GND on Top Layer "Top Layer-No Net 15" (solid, remove dead copper, pour order 348): 2183.85,480.15 2198,466 2198,40 2188.15,30.15 2086.85,30.15 2077,40 2077,466 2091.15,480.15
VDD2_1.5V_Img on Top Layer "Top Layer-No Net 4" (solid, remove dead copper, pour order 346): 19 vertices, not listed, extent 1730,30 2054,667
GND on Top Layer "Top Layer-No Net 33" (solid, remove dead copper, pour order 272): 1820,1506.85 1846.85,1480 2249.13,1480 2265,1495.87 2265,1780 2255,1790 1830,1790 1820,1780
EARTH_GND on Top Layer "Top Layer-No Net 32" (solid, remove dead copper, pour order 270): 1470,3300 1480,3290 1740,3290 1750,3300 1750,3404.96 1740,3414.96 1479.96,3414.96 1470,3405
VDD1_5V on Top Layer "Top Layer-No Net 30" (solid, remove dead copper, pour order 244): 18 vertices, not listed, extent 3580,3730 4420,4050
VDD1_1.8V_Img on Top Layer "Top Layer-No Net 28" (solid, remove dead copper, pour order 240): 17 vertices, not listed, extent 3882,3530 4420,3720
VDD1_3.3V on Top Layer "Top Layer-No Net 27" (solid, remove dead copper, pour order 238): 29 vertices, not listed, extent 3640,2670 4420,3410
GND on Top Layer "Top Layer-No Net 20" (solid, remove dead copper, pour order 224): 3940.12,4540.12 4410,4540.12 4420,4530.12 4420,4390 4410,4380 3902,4380 3902,4254 3828,4254 3828,4428
GND on Top Layer "Top Layer-No Net 20" (solid, remove dead copper, pour order 222): 3999.38,4155 4411,4155 4420,4146 4420,4040 4410,4030 3999,4030 3985,4044 3985,4140.62
GND on Top Layer "Top Layer-No Net 20" (solid, remove dead copper, pour order 220): 4029.76,3810 4410,3810 4420.25,3799.75 4420.25,3690 4410,3680 4029.25,3680 4015,3694.25 4015,3794.87
GND on Top Layer "Top Layer-No Net 20" (solid, remove dead copper, pour order 218): 3965,3455 4410,3455 4420,3445 4420,3340 4410,3330 3965,3330 3955,3340 3955,3445
GND on Top Layer "Top Layer-No Net 20" (solid, remove dead copper, pour order 216): 3956.02,3110.02 4409.98,3110.02 4420,3100 4420,2994 4410,2984 3954,2984 3945,2993 3945,3100
GND on Top Layer "Top Layer-No Net 20" (solid, remove dead copper, pour order 210): 3960,2050 4395,2050 4410,2035 4410,1945 4390,1925 3960,1925 3945,1940 3945,2035
GND on Top Layer "Top Layer-No Net 20" (solid, remove dead copper, pour order 208): 3962.5,1700 4440,1700 4460,1680 4460,1595 4440,1575 3962.5,1575 3947.5,1590 3947.5,1685
VDD1_1.35V on Top Layer "Top Layer-No Net 19" (solid, pour order 206): 3630,1610 3630,1256.46 3646.46,1240 4430,1240 4460,1270 4460,1540 4440,1560 3934.11,1560 3910,1580.64 3910,1610 3890,1630 3650,1630
VLED2 on Top Layer "Bottom Layer-No Net" (solid, remove dead copper, pour order 184): 250,440 390,300 390,39 399,30 565,30 575,40 575,340 365,550 265,550 250,535
VDD2_3.3VA on Top Layer "Top Layer-No Net 13" (solid, remove dead copper, pour order 182): 880,460 880,50 900,30 1000,30 1020,50 1020,475 1043,493.07 1043,659.19 1035.07,667.13 998.13,667.13 990.02,659.02 990.02,570.02
GND on Top Layer "Top Layer-No Net 12" (solid, remove dead copper, pour order 178): 1053,476 1053,660 1053,675 1190,675 1190,40 1180,30 1070,30 1055,40
VDD2_1.8V_Img on Top Layer "Top Layer-No Net 11" (solid, remove dead copper, pour order 176): 1240,667 1229,658 1229,608 1229,542.32 1229,40 1239,30 1355,30 1365,40 1365,470 1293,530 1293,659 1284,667
GND on Top Layer "Top Layer-No Net 10" (solid, remove dead copper, pour order 174): 1311.23,659 1311.23,535.23 1384,479 1384,462.46 1384,40 1394,30 1485,30 1495,40 1495.52,556.13 1373.31,675 1326.26,675
GND on Top Layer "Top Layer-No Net 8" (solid, remove dead copper, pour order 170): 1731,461 1686,506 1646,506 1561,591 1561,665 1571,675 1616,675 1798,480 1825,480 1855,450 1855,40 1845,30 1741,30 1731,40
GND on Top Layer "Top Layer-No Net 1" (solid, remove dead copper, pour order 160): 3968,470 3979.71,459.72 3979.71,40.47 3969.71,30.47 3844.71,30.47 3835,40 3835,460 3846,470
GND on Top Layer "Top Layer-No Net 1" (solid, remove dead copper, pour order 158): 3615,471 3626,460 3626,40 3616,30 3491,30 3481,40 3481,460 3492,471
GND on Top Layer "Top Layer-No Net 1" (solid, remove dead copper, pour order 156): 3257,470 3267,460 3267,45 3252,30 3132,30 3121.29,40.71 3121.29,460.29 3131,470
GND on Top Layer "Top Layer-No Net 1" (solid, remove dead copper, pour order 152): 2916,470 2921,465 2921,40 2911,30 2786,30 2775,40 2775,465 2780,470
GND on Top Layer "Top Layer-No Net" (solid, remove dead copper, pour order 150): 2431,470 2431,40.5 2441,30.5 2571,30.5 2581,40.5 2581,470 2565.5,485.5 2446.5,485.5
VSS on Top Layer "gn" (solid, remove dead copper, pour order 144): 18 vertices, not listed, extent 1615,2681.81 2000,3206
NetC54_2 on Top Layer "gn" (solid, remove dead copper, pour order 142): 35 vertices, not listed, extent 70,2061.81 915,2901.81
RSNS on Top Layer "TOP_LAYER_RSNS_P008" (solid, remove dead copper, pour order 8): 1790,2725.81 1795,2725.81 1795,2677.02 1805,2667.02 1835,2667.02 1845,2657.02 1845,2507.02 1840,2502.02 1765,2502.02 1760,2507.02 1760,2725.81 1765,2725.81
DRAIN on Top Layer "TOP_LAYER_DRAIN_P010" (solid, remove dead copper, pour order 10): 1727.97,2653.84 1730,2651.81 1730.08,2526.89 1725,2521.81 1690,2521.81 1685,2515.81 1685,2231.81 1680,2231.81 1600,2231.81 1600,2726.81 1647,2726.81 1647,2655.91 1655,2653.84
NetC1_1 on Top Layer "Top Layer-No Net 2" (solid, pour order 12): 1470,2151.81 1470,2058 1470,2057 1130,2056.81 1130,2151.81 1275,2151.81 1275,2436.81 1190,2436.81 1190,2661.81 1365,2661.81 1365,2151.81
NetD9_1 on Top Layer "Top Layer-No Net 6" (solid, pour order 20): 730,2776.81 805,2776.81 805,2596.81 225,2596.81 225,2781.81 595,2781.81 595,2671.81 730,2671.81
VPD on Top Layer "Top Layer-No Net 7" (solid, pour order 22): 460,2566.81 460,2271.81 1160,2271.81 1160,2981.81 1590,2981.81 1590,3051.81 1590,3206 970,3206 970,2566.81
NetD1_1 on Top Layer "gn" (solid, remove dead copper, pour order 24): 17 vertices, not listed, extent 1549.57,1506.81 1785,1791.81
12V on Top Layer "gn" (solid, remove dead copper, pour order 26): 44 vertices, not listed, extent 35,1040 2810,1409.75
NetF1_2 on Top Layer "gn" (solid, remove dead copper, pour order 30): 400,1631.81 425,1606.81 625,1606.81 650,1631.81 650,1891.81 630,1911.81 422.84,1911.81 400,1888.97
NetC54_1 on Top Layer "Top Layer-No Net 3" (solid, remove dead copper, pour order 14): 225,2566.81 435,2566.81 435,2271.81 225,2271.81
VSS on Top Layer "gn" (solid, remove dead copper, pour order 32): 460,2241.81 460,2081.81 470,2071.81 645,2071.81 660,2086.81 660,2241.81 650,2251.81 465,2251.81 460,2246.81
NetC19_2 on Top Layer "gn" (solid, remove dead copper, pour order 34): 50,1896.81 50,1361.81 100,1311.81 835,1311.81 840,1316.81 840,1486.81 830,1496.81 650,1496.81 585,1561.81 455,1561.81 400,1561.81 350,1611.81 350,1891.81 330,1911.81 65,1911.81
NetC19_1 on Top Layer "gn" (solid, remove dead copper, pour order 40): 700,1721.81 700,1623.44 655,1578.44 655,1526.3 659.49,1521.81 816.69,1521.81 835,1540.12 835,1716.81 820,1731.81 705,1731.81 700,1726.81
NetC35_1 on Top Layer "gn" (solid, remove dead copper, pour order 48): 2951,4800 2940,4789 2940,4715 2950,4705 3247.1,4705 3308.1,4644 3308.1,4504 3327.63,4484.47 3327.63,4456.87 3327.63,4429.47 3333.1,4424 3373.1,4424 3378.1,4429 3378.1,4776.9 3355,4800
GND on Top Layer "gn" (solid, remove dead copper, pour order 52): 23 vertices, not listed, extent 3137,4332.5 3385.66,4637.5
NetL6_1 on Top Layer "gn" (solid, remove dead copper, pour order 54): 17 vertices, not listed, extent 3359,4255 3530,4490
VDD2_5V on Top Layer "gn" (solid, remove dead copper, pour order 82): 19 vertices, not listed, extent 1955,30 2594.91,641
NetC139_1 on Top Layer "gn" (solid, remove dead copper, pour order 128): 535,1035 540,1040 615,1040 620,1035 620,730 615,725 560,725 555,730 555,940 535,960
GND on Top Layer "gn" (solid, remove dead copper, pour order 130): 27 vertices, not listed, extent 35,646.81 600,1025
NetL20_1 on Top Layer "gn" (solid, remove dead copper, pour order 138): 736.54,709.37 750,695.91 750,304.09 735,289.09 635,289.09 618,306.09 618,677.91 603.46,692.44 565,692.44 565,709.37
VDD1_1.1V on Top Layer "Top Layer-No Net 19" (solid, pour order 386): 3630,2100 3630,1787 3650,1767 4410,1767 4410,1905.61 3830.76,1905.81 3783,1946.69 3783,2100 3773,2110 3640,2110
NetC29_1 on Top Layer "Top Layer-No Net 22" (solid, pour order 502): 3184,2015 3239,2015 3244,2020 3244,2026 3248,2030 3305,2030 3310,2025 3310,1975 3305,1970 3249,1970 3244,1975 3244,1981 3240,1985 3184,1985
NetC33_1 on Top Layer "Top Layer-No Net 23" (solid, pour order 508): 20 vertices, not listed, extent 2940,2005.41 3454.76,2290
NetC38_1 on Top Layer "Top Layer-No Net 22" (solid, pour order 512): 3184,1490 3239,1490 3244,1495 3244,1501 3248,1505 3305,1505 3310,1500 3310,1450 3305,1445 3249,1445 3244,1450 3244,1456 3240,1460 3184,1460
NetC41_1 on Top Layer "Top Layer-No Net 23" (solid, pour order 514): 20 vertices, not listed, extent 2939.02,1480.41 3453.78,1765
NetC52_1 on Top Layer "Top Layer-No Net 23" (solid, pour order 520): 20 vertices, not listed, extent 2940,2530.41 3454.76,2815
NetC50_1 on Top Layer "Top Layer-No Net 22" (solid, pour order 522): 3184,2540 3239,2540 3244,2545 3244,2551 3248,2555 3305,2555 3310,2550 3310,2500 3305,2495 3249,2495 3244,2500 3244,2506 3240,2510 3184,2510
NetC50_1 on Top Layer "Top Layer-No Net 25" (solid, pour order 524): 3500,2620 3558,2620 3558,2430 3500,2430
NetJ19_6 on Top Layer "Top Layer-No Net 49" (solid, remove dead copper, pour order 632): 0,4479 211,4479 240,4450 240,4154 224,4138 9,4138 0,4147
12V_PoE on Top Layer "Top Layer-No Net 50" (solid, pour order 636): 2300,1365 2219.65,1285 1566,1285 1430,1421 1334,1421 1334,1440 1425,1440 1425,1454 1470.13,1454 1484.13,1440 1544.69,1440 1545,1494 1800,1492 1850,1450 2300,1450
NetC20_1 on Top Layer "Top Layer-No Net 51" (solid, pour order 638): 20 vertices, not listed, extent 860,1420 1140,1840
12V_Adapter on Top Layer "Top Layer-No Net 52" (solid, pour order 640): 21 vertices, not listed, extent 1120,1420 1323,1840
GND on Bottom Layer "Top Layer-No Net 36" (solid, remove dead copper, pour order 668): 24 vertices, not listed, extent 0,-1 4497.63,4882
12V_Adapter on Bottom Layer "Bottom Layer-No Net 7" (solid, pour order 666): 1500,1440 1630.16,1440 1630.16,1849.51 1629.61,1850.06 1239,1850 1239,1711 1240,1710 1469.75,1710 1469.75,1440 1499,1440
VDD1_1.8V_codec on Bottom Layer "Top Layer-No Net 39" (solid, pour order 580): 3640,2650 3700,2650 3710,2640 3710,2370 3730,2350 3850,2350 3940,2260 4410,2260 4420,2250 4420,2140 4410,2130 3920,2130 3692,2130 3630,2192 3630,2640
VDD1_1.1V on Bottom Layer "Top Layer-No Net 19" (solid, pour order 576): 3630,2100 3630,1787 3650,1767 4410,1767 4410,1905.61 3830.76,1905.81 3783,1946.69 3783,2100 3773,2110 3640,2110
VDD1_1.35V on Bottom Layer "Top Layer-No Net 19" (solid, pour order 572): 3630,1610 3630,1256.46 3646.46,1240 4430,1240 4460,1270 4460,1540 4440,1560 3934.11,1560 3910,1580.64 3910,1610 3890,1630 3650,1630
VDD1_1.5V_Img on Bottom Layer "Top Layer-No Net 20" (solid, remove dead copper, pour order 570): 4029.76,2622 4410,2622 4420.25,2611.75 4420.25,2502 4410,2492 4029.25,2492 4015,2506.25 4015,2606.87
VDD1_2.8V_Img on Bottom Layer "Top Layer-No Net 16" (solid, pour order 494): 3880,2900 3890,2890 3950,2890 3960,2880 4000,2880 4050,2830 4410,2830 4420,2840 4420,2950 4410,2960 3890,2960 3880,2950
VDD1_3.3V on Bottom Layer "Top Layer-No Net 27" (solid, remove dead copper, pour order 564): 29 vertices, not listed, extent 3640,2670 4420,3410
VDD1_3.3VA on Bottom Layer "Top Layer-No Net 20" (solid, remove dead copper, pour order 562): 4029.76,4372 4410,4372 4420.25,4361.75 4420.25,4252 4410,4242 4029.25,4242 4015,4256.25 4015,4356.87
VDD1_5V on Bottom Layer "Signal Layer 2-No Net 9" (solid, pour order 560): 3560,4134 3575,4149 4176.85,4149 4190,4135.85 4190,4030 4210,4010 4410,4010 4420,4000 4420,3850 4410,3840 3687,3840 3687,4020 3580,4020 3560,4040
NetC76_1 on Bottom Layer "Bottom Layer-No Net 2" (solid, pour order 552): 2128,988 2138,978 2138,957 2138,678 2128,668 2068,668 2058,678 2058,978 2068,988
NetC39_1 on Bottom Layer "Bottom Layer-No Net 2" (solid, pour order 544): 3240,3980 3250,3990 3580,3990 3590,3980 3590,3920 3580,3910 3250,3910 3240,3920
NetC46_1 on Bottom Layer "Bottom Layer-No Net 2" (solid, pour order 534): 3240,3155 3250,3165 3580,3165 3590,3155 3590,3095 3580,3085 3250,3085 3240,3095
VDD2_5V on Bottom Layer "Bottom Layer-No Net 1" (solid, pour order 440): 39 vertices, not listed, extent 930,50 4377,1190.64
PGND on Bottom Layer "Bottom Layer-PGND" (solid, remove dead copper, pour order 374): 30,3065 30,2140 165,2005 2620,2005 2775,2160 2775,3050 2640,3185 150,3185
NetC1_1 on Bottom Layer "Bottom Layer-No Net 9" (solid, remove dead copper, pour order 350): 1331,2418 1418,2505 1761,2505 1789,2477 1789,2394 1781,2386 1597,2386 1574,2363 1574,2019 1560,2005 1345,2005 1331,2019
NetC139_1 on Bottom Layer "gn" (solid, remove dead copper, pour order 310): 535,1025 550,1040 600,1040 615,1025 615,746.81 598.19,730 549.42,730 535,744.42
EARTH_GND on Bottom Layer "Signal Layer 1-No Net 2" (solid, remove dead copper, pour order 268): 1220,3255 1220,3910 930,3910 878.19,3961.81 553.19,3961.81 465,4050 100,4050 30,3980 30,3305 105,3230 1195,3230
NetJ19_6 on Bottom Layer "Bottom Layer-No Net 6" (solid, remove dead copper, pour order 260): 17 vertices, not listed, extent 30,4110 310,4490
VSS on Bottom Layer "Bottom Layer-No Net 5" (solid, remove dead copper, pour order 256): 19 vertices, not listed, extent 460,2005 1995,3207
12V on Bottom Layer "Bottom Layer-No Net 4" (solid, remove dead copper, pour order 254): 35,1070 50,1055 605,1055 625,1075 625,1250 590,1285 65,1285 35,1255
12V on Bottom Layer "Bottom Layer-No Net 3" (solid, remove dead copper, pour order 252): 2565,1035 2565,1130 2590,1155 2670,1155 2787.5,1272.5 2967.5,1272.5 3219.71,1524.71 3208.02,4815 2955,4815 2918,4778 2918,1848 2419,1349 2419,1035
VPD on Bottom Layer "gn" (solid, remove dead copper, pour order 140): 1300,3190 1300,3096.81 1320,3076.81 1325,3071.81 1415,3071.81 1540,3071.81 1565,3096.81 1565,3190 1555,3200 1310,3200
NetC19_2 on Bottom Layer "gn" (solid, remove dead copper, pour order 36): 50,1896.81 50,1361.81 100,1311.81 690,1311.81 705,1326.81 705,1481.81 690,1496.81 615,1496.81 550,1561.81 400,1561.81 350,1611.81 350,1891.81 330,1911.81 65,1911.81 50,1896.81
NetC19_1 on Bottom Layer "gn" (solid, remove dead copper, pour order 42): 605,1631.81 605,1546.81 620,1531.81 630,1521.81 700,1521.81 710,1521.81 720,1531.81 720,1626.81 700,1646.81 615,1646.81 605,1636.81
NetC29_1 on Bottom Layer "Bottom Layer-No Net 2" (solid, pour order 504): 3240,2030 3250,2040 3271,2040 3550,2040 3560,2030 3560,1970 3550,1960 3250,1960 3240,1970
NetC38_1 on Bottom Layer "Bottom Layer-No Net 2" (solid, pour order 516): 3240,1505 3250,1515 3271,1515 3550,1515 3560,1505 3560,1445 3550,1435 3250,1435 3240,1445
NetC50_1 on Bottom Layer "Bottom Layer-No Net 2" (solid, pour order 528): 3240,2555 3250,2565 3580,2565 3590,2555 3590,2495 3580,2485 3250,2485 3240,2495
EARTH_GND on Bottom Layer "Signal Layer 1-No Net 2" (solid, remove dead copper, pour order 630): 30,3980 100,4050 465,4050 553.19,3961.81 878.19,3961.81 930,3910 1227.5,3910 1227.5,3252.5 1205,3230 105,3230 30,3305
VDD2_1.8V_Codec on Signal Layer 2 "Signal Layer 2-No Net 1" (solid, remove dead copper, pour order 622): 3785,770 3795,780 4181,780 4190,771 4190,450.14 3985,303.72 3985,40 3975,31 3675,30 3665,40 3665,290 3705,320 3705,400 3785,457.31
VDD2_1.35V on Signal Layer 2 "Signal Layer 2-No Net 1" (solid, remove dead copper, pour order 620): 3355,770 3365,780 3738,780 3749,769 3749,469.86 3635,388.43 3635,40 3625,31 3325,30 3315,40 3315,290 3355,320
VDD2_1.1V on Signal Layer 2 "Signal Layer 2-No Net 1" (solid, remove dead copper, pour order 618): 2965,770 2975,780 3310,780 3320,770 3320,329.71 3285,304.71 3285,40 3275,31 2975,30 2965,40
VDD1_1.8V_codec on Signal Layer 2 "Top Layer-No Net 39" (solid, pour order 582): 3640,2650 3700,2650 3710,2640 3710,2370 3730,2350 3850,2350 3940,2260 4410,2260 4420,2250 4420,2140 4410,2130 3920,2130 3692,2130 3630,2192 3630,2640
VDD1_1.1V on Signal Layer 2 "Top Layer-No Net 19" (solid, pour order 578): 3630,2100 3630,1787 3650,1767 4410,1767 4410,1905.61 3830.76,1905.81 3783,1946.69 3783,2100 3773,2110 3640,2110
VDD1_1.35V on Signal Layer 2 "Top Layer-No Net 19" (solid, pour order 574): 3630,1610 3630,1256.46 3646.46,1240 4430,1240 4460,1270 4460,1540 4440,1560 3934.11,1560 3910,1580.64 3910,1610 3890,1630 3650,1630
